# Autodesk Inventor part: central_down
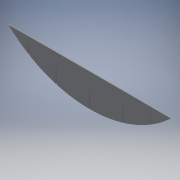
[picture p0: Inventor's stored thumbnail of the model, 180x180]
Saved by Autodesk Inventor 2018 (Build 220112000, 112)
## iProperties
Created: 2019-03
Part Number: central_down
Material: Generic
Document SubType Name: Modeling
Designer: vpimentel
Density: 1 g/cm^3
Appearance: Default
Author: vpimentel
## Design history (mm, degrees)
sketch "Sketch1"
  geometry: L1 (275, 0)-(-275, 0); L2 (0, 0)-(0, -110); L3 (-1.45, -109.997)-(-1.45, -54.997); L4 (-1.45, -54.997)-(1.45, -54.997); L5 (1.45, -54.997)-(1.45, -109.997); L6 (111.45, -94.108)-(111.45, -47.108); L7 (111.45, -47.108)-(114.35, -47.108); L8 (114.35, -47.108)-(114.35, -93.252); L9 (204.35, -53.657)-(204.35, -25.657); L10 (204.35, -25.657)-(207.25, -25.657); L11 (207.25, -25.657)-(207.25, -51.91); L12 (-114.35, -93.252)-(-114.35, -47.108); L13 (-114.35, -47.108)-(-111.45, -47.108); L14 (-111.45, -47.108)-(-111.45, -94.108); L15 (-207.25, -51.91)-(-207.25, -25.657); L16 (-207.25, -25.657)-(-204.35, -25.657); L17 (-204.35, -25.657)-(-204.35, -53.657); A1 r 398.75 centre (0, 288.75) between (114.35, -93.252) and (204.35, -53.657); A2 r 398.75 centre (0, 288.75) between (207.25, -51.91) and (275, 0); A3 r 398.75 centre (0, 288.75) between (1.45, -109.997) and (111.45, -94.108); A4 r 398.75 centre (0, 288.75) between (-111.45, -94.108) and (-1.45, -109.997); A5 r 398.75 centre (0, 288.75) between (-275, 0) and (-207.25, -51.91); A6 r 398.75 centre (0, 288.75) between (-204.35, -53.657) and (-114.35, -93.252); 2 further points
  constraints: 34 end point, 12 point on circle, 7 parallel, 6 centre point, 3 point on line, 2 midpoint, 1 coincident, 1 horizontal, 1 vertical
  dimensions: "d0" = 550 distance of L1.start L1.end; "d1" = 110 distance of L2.start L2.end; "d2" = 2.9 distance of L3.start L5.end; "d7" = 55 distance of L3.start L3.end; "d9" = 110 distance between parallel lines of L6 L5; "d10" = 47 distance of L6.start L6.end; "d11" = 90 distance between parallel lines of L9 L8; "d12" = 28 distance of L9.start L9.end; "d13" = 2.9 distance between parallel lines of L6 L8 (= d2); "d14" = 2.9 distance between parallel lines of L11 L9 (= d13); "d15" = 2.9 distance between parallel lines of L12 L14 (= d2); "d16" = 2.9 distance between parallel lines of L15 L17 (= d15)
extrude "Extrusion1" new body sketch "Sketch1" distance "d18" = 2.9 (= d2); taper "d19" = 0 deg
body "Solid1"
